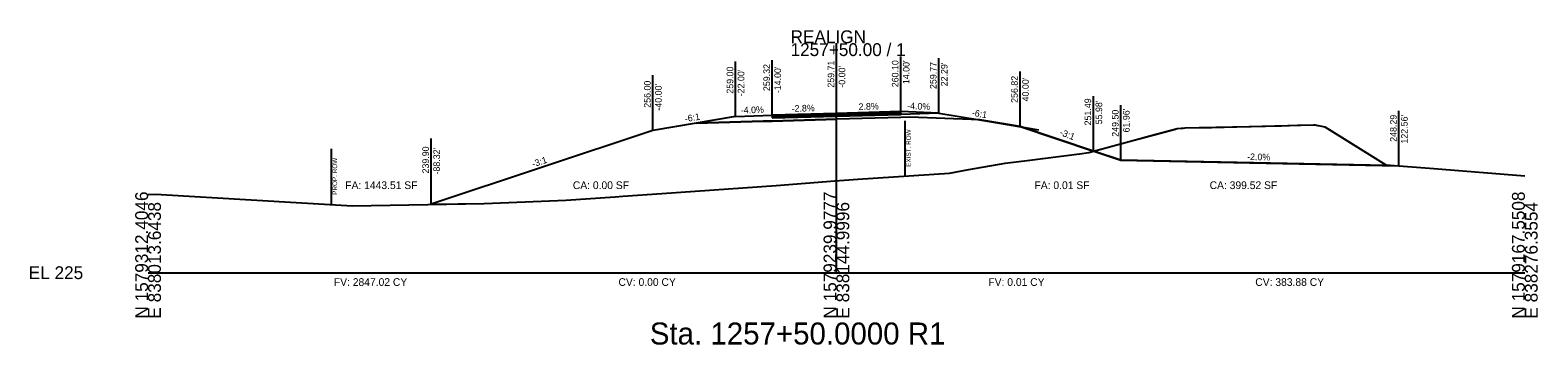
# Model space of a CAD drawing. Extents: x -26 to 6303, y -16 to 9563.
# Drawn here: x 2974.3 to 3302.8, y 9484.3 to 9552.8 of the extents above; entities that cross this region are included whole.
import ezdxf

# ---------------------------------------------------------------- set-up
doc = ezdxf.new("R2010")
doc.units = 0
for name, color, linetype in [('ASPHALT_19MM1', 7, 'Continuous'), ('ASPHALT_9_5MM1', 7, 'Continuous'), ('CONST_LV3', 7, 'Continuous'), ('CONST_PROF_LV1', 7, 'Continuous'), ('Draft_XS_Grid', 7, 'Continuous'), ('Draft_XS_Text', 7, 'Continuous'), ('DTM_TEMP_DROP', 7, 'Continuous'), ('DTM_X_FLOW_ARROWS', 7, 'Continuous'), ('DTM_X_GROUND', 7, 'Continuous'), ('TRANS_BRIDGE', 7, 'Continuous'), ('XS_CELL', 7, 'Continuous'), ('XS_M_SHAPES_EARTHWORK', 7, 'Continuous'), ('XS_P_GROUND', 7, 'Continuous'), ('XS_P_NULL_POINT', 7, 'Continuous'), ('XS_P_ROW', 7, 'Continuous'), ('XS_P_SHOULDER', 7, 'Continuous'), ('XS_P_SUBGRADE_GRANULAR', 7, 'Continuous'), ('XS_P_TX_CLEARZONE', 7, 'Continuous'), ('XS_P_TX_FS_BS', 7, 'Continuous'), ('XS_PLAN_CLEAR_ZONE', 7, 'Continuous'), ('XS_SHEET_EW_TX_AREA', 7, 'Continuous'), ('XS_SHEET_EW_TX_VOLUME', 7, 'Continuous'), ('XS_X_ROW', 7, 'Continuous')]:
    doc.layers.add(name, color=color, linetype=linetype)

msp = doc.modelspace()

# ---------------------------------------------------------------- linework, layer by layer
at = {"layer": 'ASPHALT_19MM1'}
msp.add_lwpolyline([(3136, 9533.72), (3136, 9533.72), (3136, 9533.72), (3150, 9534.11), (3150, 9534.11), (3164, 9534.5), (3164, 9534.5), (3164, 9534.77), (3150, 9534.38), (3150, 9534.38), (3136, 9533.99), (3136, 9533.99), (3136, 9533.72)], dxfattribs=at)
at = {"layer": 'ASPHALT_9_5MM1'}
msp.add_lwpolyline([(3136, 9534.2), (3136, 9534.2), (3136, 9534.2), (3150, 9534.59), (3150, 9534.59), (3164, 9534.98), (3164, 9534.98), (3164, 9535.1), (3150, 9534.71), (3150, 9534.71), (3136, 9534.32), (3136, 9534.32), (3136, 9534.2)], dxfattribs=at)
at = {"layer": 'CONST_LV3'}
for points in [[(3150, 9534.71), (3164, 9534.43)], [(3172.29, 9534.77), (3172.29, 9534.77), (3164, 9534.43)], [(3119.53, 9532.59), (3110, 9531)], [(3181.25, 9533.28), (3194, 9531.15)]]:
    msp.add_lwpolyline(points, dxfattribs=at)
at = {"layer": 'DTM_X_GROUND'}
msp.add_lwpolyline([(3000, 9517.05), (3001.61, 9517.11), (3044.55, 9514.6), (3073.21, 9515.1), (3085.74, 9515.58), (3091.02, 9515.78), (3101.77, 9516.56), (3103.44, 9516.67), (3111.97, 9517.27), (3136.89, 9519.01), (3149.63, 9520.04), (3151.66, 9520.19), (3154.66, 9520.4), (3174.65, 9521.72), (3178.82, 9522.45), (3186.8, 9523.87), (3192.16, 9524.54), (3194.99, 9524.91), (3203.54, 9525.97), (3204.51, 9526.1), (3204.97, 9526.22), (3213.8, 9528.6), (3214.61, 9528.81), (3215.95, 9529.16), (3223.86, 9531.29), (3224.22, 9531.39), (3225.56, 9531.49), (3226, 9531.56), (3229.05, 9531.61), (3239.97, 9531.83), (3253.93, 9532.21), (3254.15, 9532.22), (3254.23, 9532.2), (3256.4, 9531.8), (3259.48, 9529.86), (3269.68, 9523.51), (3280.14, 9522.7), (3300, 9521.12)], dxfattribs=at)
at = {"layer": 'XS_CELL'}
for p, q in [((3150, 9500), (3150, 9550)), ((3000, 9500), (3150, 9500)), ((3150, 9500), (3300, 9500))]:
    msp.add_line(p, q, dxfattribs=at)
at = {"layer": 'XS_M_SHAPES_EARTHWORK'}
msp.add_lwpolyline([(3061.68, 9514.9), (3073.21, 9515.1), (3085.74, 9515.58), (3091.02, 9515.78), (3101.77, 9516.56), (3103.44, 9516.67), (3111.97, 9517.27), (3136.89, 9519.01), (3149.63, 9520.04), (3151.66, 9520.19), (3154.66, 9520.4), (3174.65, 9521.72), (3178.82, 9522.45), (3186.8, 9523.87), (3192.16, 9524.54), (3194.99, 9524.91), (3203.54, 9525.97), (3204.51, 9526.1), (3204.97, 9526.22), (3205.98, 9526.49), (3190, 9531.82), (3181.25, 9533.28), (3166, 9533.89), (3164, 9533.83), (3150, 9533.44), (3136, 9533.05), (3134, 9532.99), (3119.53, 9532.59), (3110, 9531)], close=True, dxfattribs=at)
at = {"layer": 'XS_P_GROUND'}
for points in [[(3172.29, 9534.77), (3190, 9531.82), (3205.98, 9526.49)], [(3172.29, 9534.77), (3190, 9531.82), (3211.96, 9524.5)], [(3128, 9534), (3110, 9531), (3061.68, 9514.9)], [(3211.96, 9524.5), (3240.01, 9523.94)], [(3240.01, 9523.94), (3272.56, 9523.29)]]:
    msp.add_lwpolyline(points, dxfattribs=at)
at = {"layer": 'XS_P_ROW'}
msp.add_line((3040, 9514.98), (3040, 9526.98), dxfattribs=at)
at = {"layer": 'XS_P_SHOULDER'}
for points in [[(3128, 9534), (3128, 9534), (3136, 9534.32)], [(3172.29, 9534.77), (3172.29, 9534.77), (3164, 9535.1)]]:
    msp.add_lwpolyline(points, dxfattribs=at)
at = {"layer": 'XS_P_SUBGRADE_GRANULAR'}
for points in [[(3119.53, 9532.59), (3119.53, 9532.59), (3134, 9532.99), (3134, 9532.99), (3136, 9533.05)], [(3136, 9533.05), (3136, 9533.05), (3150, 9533.44)], [(3164, 9533.83), (3150, 9533.44), (3150, 9533.44)], [(3181.25, 9533.28), (3181.25, 9533.28), (3166, 9533.89), (3164, 9533.83), (3164, 9533.83)]]:
    msp.add_lwpolyline(points, dxfattribs=at)
at = {"layer": 'XS_P_TX_CLEARZONE'}
for p, q in [((3128, 9534), (3128, 9546)), ((3136, 9534.32), (3136, 9546.32)), ((3150, 9534.71), (3150, 9546.71)), ((3164, 9535.1), (3164, 9547.1)), ((3172.29, 9534.77), (3172.29, 9546.77)), ((3172.29, 9534.77), (3172.29, 9546.77)), ((3110, 9531), (3110, 9543)), ((3190, 9531.82), (3190, 9543.82)), ((3205.98, 9526.49), (3205.98, 9538.49)), ((3211.96, 9524.5), (3211.96, 9536.5)), ((3272.56, 9523.29), (3272.56, 9535.29)), ((3061.68, 9514.9), (3061.68, 9529.25))]:
    msp.add_line(p, q, dxfattribs=at)
at = {"layer": 'XS_P_TX_FS_BS'}
msp.add_lwpolyline([(3205.98, 9526.49), (3213.8, 9528.6), (3219.91, 9530.23), (3224.22, 9531.39), (3226, 9531.56), (3231.78, 9531.67), (3237.24, 9531.77), (3243.46, 9531.92), (3246.95, 9532.02), (3250.44, 9532.11), (3254.15, 9532.22), (3256.4, 9531.8), (3262.03, 9528.27), (3266.84, 9525.28), (3269.95, 9523.34), (3211.96, 9524.5)], close=True, dxfattribs=at)
at = {"layer": 'XS_PLAN_CLEAR_ZONE'}
msp.add_lwpolyline([(3136, 9533.99), (3136, 9533.99), (3136, 9533.99), (3150, 9534.38), (3150, 9534.38), (3164, 9534.77), (3164, 9534.77), (3164, 9534.98), (3150, 9534.59), (3150, 9534.59), (3136, 9534.2), (3136, 9534.2), (3136, 9533.99)], dxfattribs=at)
at = {"layer": 'XS_X_ROW'}
msp.add_line((3165.01, 9521.08), (3165.01, 9533.08), dxfattribs=at)

# ---------------------------------------------------------------- texts
at = {"layer": 'CONST_PROF_LV1'}
for p in [(3205.9, 9526.37), (3061.6, 9514.78)]:
    msp.add_text('X', height=0.24, dxfattribs=at).set_placement(p)
at = {"layer": 'Draft_XS_Grid'}
msp.add_text('-', height=0.0001, dxfattribs=at).set_placement((3000, 9500))
at = {"layer": 'Draft_XS_Text'}
msp.add_text('Sta. 1257+50.0000 R1', height=4.8, dxfattribs=at).set_placement((3109.33, 9484.35))
at = {"layer": 'DTM_TEMP_DROP'}
for p in [(3135.92, 9534.2), (3149.92, 9534.59), (3163.92, 9534.98)]:
    msp.add_text('X', height=0.24, dxfattribs=at).set_placement(p)
at = {"layer": 'DTM_X_FLOW_ARROWS'}
msp.add_text('X', height=0.24, dxfattribs=at).set_placement((3272.48, 9523.17))
at = {"layer": 'TRANS_BRIDGE'}
for p in [(3205.9, 9526.37), (3061.6, 9514.78)]:
    msp.add_text('X', height=0.24, dxfattribs=at).set_placement(p)
at = {"layer": 'XS_CELL'}
for s, p in [('REALIGN', (3140, 9550)), ('1257+50.00 / 1', (3140, 9547.2)), ('EL 225', (2974, 9498.6))]:
    msp.add_text(s, height=2.8, dxfattribs=at).set_placement(p)
for s, p in [('N 1579312.4046', (3000, 9490)), ('E 838013.6438', (3002.8, 9490)), ('N 1579239.9777', (3150, 9490)), ('E 838144.9996', (3152.8, 9490)), ('N 1579167.5508', (3300, 9490)), ('E 838276.3554', (3302.8, 9490))]:
    msp.add_text(s, height=2.8, rotation=90, dxfattribs=at).set_placement(p)
at = {"layer": 'XS_P_GROUND'}
for p in [(3109.92, 9530.88), (3193.92, 9531.03)]:
    msp.add_text('X', height=0.24, dxfattribs=at).set_placement(p)
at = {"layer": 'XS_P_NULL_POINT'}
for p in [(3172.21, 9534.65), (3189.92, 9531.7)]:
    msp.add_text('X', height=0.24, dxfattribs=at).set_placement(p)
at = {"layer": 'XS_P_ROW'}
msp.add_text('PROP. ROW', height=1, rotation=90, dxfattribs=at).set_placement((3041.2, 9516.98))
at = {"layer": 'XS_P_SHOULDER'}
for p in [(3127.92, 9533.88), (3172.21, 9534.65)]:
    msp.add_text('X', height=0.24, dxfattribs=at).set_placement(p)
at = {"layer": 'XS_P_SUBGRADE_GRANULAR'}
msp.add_text('X', height=0.24, dxfattribs=at).set_placement((3211.89, 9524.38))
at = {"layer": 'XS_P_TX_CLEARZONE'}
for s, p in [('259.00', (3127.52, 9539.01)), ("-22.00'", (3129.92, 9538.43)), ('259.32', (3135.52, 9539.57)), ("-14.00'", (3137.92, 9539.11)), ('259.71', (3149.52, 9540.32)), ("-0.00'", (3151.92, 9540.32)), ('260.10', (3163.52, 9540.41)), ("14.00'", (3165.92, 9541.08)), ('259.77', (3171.81, 9540.02)), ("22.29'", (3174.21, 9540.61)), ('256.00', (3109.52, 9535.94)), ("-40.00'", (3111.92, 9535.32)), ('256.82', (3189.52, 9537)), ("40.00'", (3191.92, 9537.32)), ('251.49', (3205.5, 9532.09)), ("55.98'", (3207.9, 9532.33)), ('249.50', (3211.48, 9529.62)), ("61.96'", (3213.88, 9530.56)), ('248.29', (3272.08, 9528.52)), ("122.56'", (3274.48, 9528.13)), ('239.90', (3061.2, 9521.62)), ("-88.32'", (3063.6, 9521.39))]:
    msp.add_text(s, height=1.44, rotation=90, dxfattribs=at).set_placement(p)
at = {"layer": 'XS_P_TX_FS_BS'}
for s, rotation, p in [('-6:1', 9.4642, (3117.08, 9532.79)), ('-4.0%', 2.2906, (3129.18, 9534.65)), ('-2.8%', 1.6039, (3140.25, 9535.04)), ('2.8%', 1.6039, (3154.84, 9535.45)), ('-4.0%', 357.7095, (3165.38, 9535.65)), ('-6:1', 350.5377, (3179.42, 9534.19)), ('-3:1', 338.7478, (3198.52, 9530.04)), ('-3:1', 18.4332, (3083.93, 9522.94)), ('-2.0%', 358.8542, (3239.48, 9524.55))]:
    msp.add_text(s, height=1.44, rotation=rotation, dxfattribs=at).set_placement(p)
at = {"layer": 'XS_SHEET_EW_TX_AREA'}
for s, p in [('FA: 1443.51 SF', (3042.97, 9518.22)), ('CA: 0.00 SF', (3092.56, 9518.22)), ('FA: 0.01 SF', (3193.16, 9518.22)), ('CA: 399.52 SF', (3231.32, 9518.22))]:
    msp.add_text(s, height=1.68, dxfattribs=at).set_placement(p)
at = {"layer": 'XS_SHEET_EW_TX_VOLUME'}
for s, p in [('FV: 2847.02 CY', (3040.49, 9497.12)), ('CV: 0.00 CY', (3102.51, 9497.12)), ('FV: 0.01 CY', (3183.11, 9497.12)), ('CV: 383.88 CY', (3241.27, 9497.12))]:
    msp.add_text(s, height=1.68, dxfattribs=at).set_placement(p)
at = {"layer": 'XS_X_ROW'}
msp.add_text('EXIST. ROW', height=1, rotation=90, dxfattribs=at).set_placement((3166.21, 9523.08))

doc.saveas('drawing.dxf')
